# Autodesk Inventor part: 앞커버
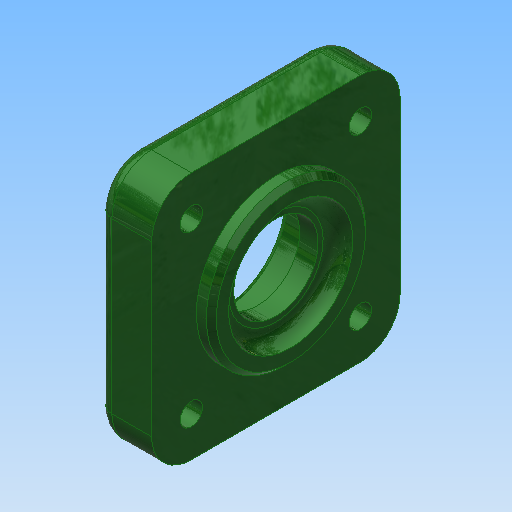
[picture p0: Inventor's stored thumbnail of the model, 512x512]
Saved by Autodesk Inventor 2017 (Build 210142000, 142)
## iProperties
Created: 2018-07
Part Number: 앞커버
Material: 알루미늄 6061
Document SubType Name: Modeling
Designer: mduedu
Density: 1 g/cm^3
Appearance: 매끄러움 - 짙은 산림 녹색
Author: mduedu
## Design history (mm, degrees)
sketch "스케치1"
  geometry: C1 r 16 at (0, 0); 1 further point
  constraints: 1 centre point, 1 coincident
  dimensions: "d0" = 32 diameter of C1
extrude "돌출1" new body sketch "스케치1" distance "d1" = 3; taper "d2" = 0 deg
sketch "스케치2"
  geometry: L1 (-25, -25)-(25, -25); L2 (25, -25)-(25, 25); L3 (25, 25)-(-25, 25); L4 (-25, 25)-(-25, -25); L5 (-25, -25)-(25, 25); L6 (25, -25)-(-25, 25); 1 further point
  constraints: 12 end point, 2 midpoint, 2 parallel, 1 horizontal, 1 perpendicular
  dimensions: "d3" = 50 distance of L3.end L2.end; "d4" = 50 distance of L2.end L1.end
extrude "돌출2" join sketch "스케치2" distance "d5" = 11; taper "d6" = 0 deg
hole "구멍1" diameter "d9" = 25; stored, may be unused: countersink angle "d13" = 90 deg, drill point angle "d15" = 0 deg; dims "d7" = 10, "d8" = 10, "d10" = 6, "d11" = 4, "d12" = 2, "d14" = 3
sketch "스케치3"
  geometry: C1 r 12.5 at (0, 0); 1 further point
  constraints: 1 centre point, 1 coincident
  dimensions: "d16" = 25 diameter of C1
extrude "돌출3" cut sketch "스케치3" distance "d17" = 7.3; taper "d18" = 0 deg
sketch "스케치4"
  geometry: C1 r 8.5 at (0, 0); 1 further point
  constraints: 1 centre point, 1 coincident
  dimensions: "d19" = 17 diameter of C1
extrude "돌출4" cut sketch "스케치4" stored distance "d20" = 7.3; taper "d21" = 0 deg
chamfer "모따기1" distance "d22" = 0.7; stored, may be unused: second distance "d23" = 2, angle "d24" = 30 deg
fillet "모깎기1" dims "d25" = 0.3
fillet "모깎기2" dims "d26" = 3
fillet "모깎기3" dims "d27" = 8
sketch "스케치5"
  geometry: L1 (25, -17)-(25, 17) reference; L2 (17, 25)-(-17, 25) reference; L3 (-25, 17)-(-25, -17) reference; L4 (-17, -25)-(17, -25) reference; C1 r 12.904 at (0, 0) reference; A1 r 8 centre (17, -17) between (17, -25) and (25, -17) reference; A2 r 8 centre (17, 17) between (25, 17) and (17, 25) reference; A3 r 8 centre (-17, 17) between (-17, 25) and (-25, 17) reference; A4 r 8 centre (-17, -17) between (-25, -17) and (-17, -25) reference; 5 further points
  constraints: 4 coincident
hole "구멍2" sketch "스케치5" at (-17, 17), (17, 17), (17, -17), (-17, -17) diameter "d28" = 4.5; stored, may be unused: countersink angle "d32" = 90 deg, drill point angle "d34" = 0 deg; dims "d29" = 6, "d30" = 8, "d31" = 4.6, "d33" = 3
fillet "모깎기4" dims "d35" = 3
chamfer "모따기2" distance "d36" = 1; stored, may be unused: second distance "d37" = 2, angle "d38" = 45 deg
node "솔리드1"
node "투영된 루프1"
